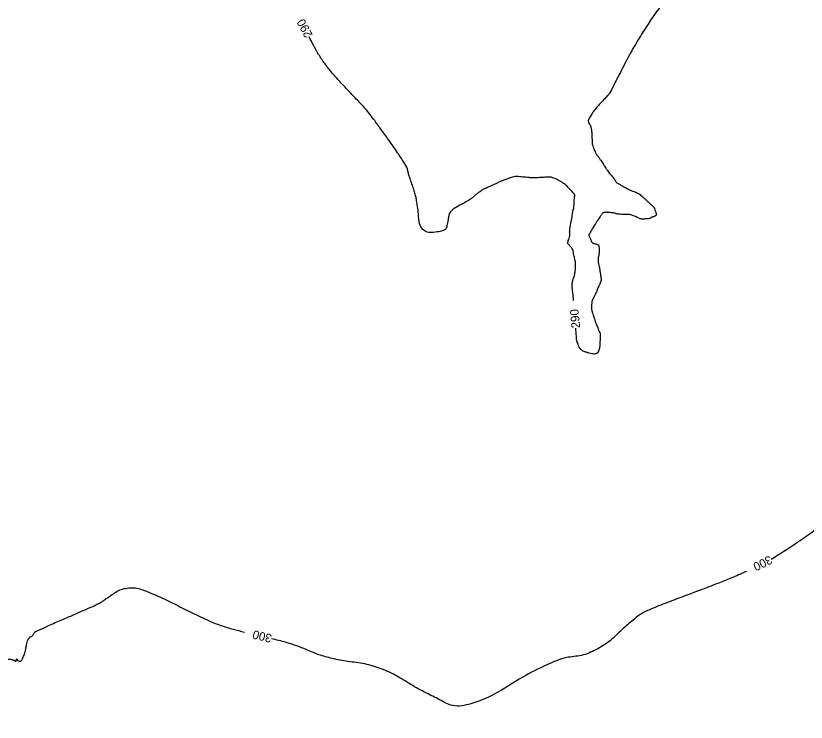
# Model space of a CAD drawing. Extents: x -475575 to -473225, y -1116053 to -1114104.
# Drawn here: x -475129.4 to -474761.3, y -1114773.1 to -1114444.1 of the extents above; entities that cross this region are included whole.
import ezdxf

# ---------------------------------------------------------------- set-up
doc = ezdxf.new("R2010")
doc.units = 0
doc.layers.add('Vrstevnice_hlavni', color=7, linetype='Continuous')
doc.layers.add('Vrstevnice_popis', color=7, linetype='Continuous')

msp = doc.modelspace()

# ---------------------------------------------------------------- linework, layer by layer
at = {"layer": 'Vrstevnice_hlavni'}
for points in [[(-475049.76, -1114348.75), (-475050.03, -1114349.06), (-475050.19, -1114349.2), (-475050.39, -1114349.32), (-475050.61, -1114349.44), (-475051.19, -1114349.58), (-475052.1, -1114349.76), (-475053.36, -1114349.96), (-475056.71, -1114349.42), (-475062.13, -1114348.12), (-475069.64, -1114346.09), (-475075.28, -1114345.23), (-475079.04, -1114345.54), (-475080.93, -1114347.03), (-475082.38, -1114348.43), (-475083.41, -1114349.73), (-475084.01, -1114350.95), (-475084.63, -1114352.12), (-475085.26, -1114353.26), (-475085.91, -1114354.37), (-475086.64, -1114355.71), (-475087.48, -1114357.27), (-475088.4, -1114359.07), (-475090.61, -1114362.26), (-475094.1, -1114366.84), (-475098.87, -1114372.82), (-475103.89, -1114377.82), (-475109.16, -1114381.82), (-475114.67, -1114384.84), (-475118.65, -1114387.53), (-475121.08, -1114389.89), (-475121.98, -1114391.93), (-475122.62, -1114393.48), (-475123, -1114394.53), (-475123.13, -1114395.1), (-475123.36, -1114395.77), (-475123.67, -1114396.56), (-475124.09, -1114397.45), (-475125.66, -1114400.87), (-475128.41, -1114406.82), (-475132.32, -1114415.29), (-475135.87, -1114422.74), (-475139.04, -1114429.17), (-475141.85, -1114434.59), (-475145.43, -1114439.9), (-475149.77, -1114445.11), (-475154.89, -1114450.23), (-475159.45, -1114455.46), (-475163.47, -1114460.8), (-475166.95, -1114466.26), (-475169.43, -1114470.03), (-475170.91, -1114472.1), (-475171.4, -1114472.49), (-475171.83, -1114472.96), (-475172.18, -1114473.51), (-475172.46, -1114474.16), (-475172.97, -1114474.88), (-475173.69, -1114475.68), (-475174.63, -1114476.54), (-475175.57, -1114477.42), (-475176.5, -1114478.32), (-475177.42, -1114479.22), (-475178.83, -1114480.41), (-475180.73, -1114481.89), (-475183.12, -1114483.65), (-475185.77, -1114486.73), (-475188.68, -1114491.12), (-475191.86, -1114496.83), (-475194.68, -1114500.53), (-475197.14, -1114502.21), (-475199.25, -1114501.88), (-475200.83, -1114501.68), (-475201.89, -1114501.59), (-475202.96, -1114501.67)], [(-474824.9, -1114433.68), (-474834.97, -1114447.99), (-474839.72, -1114455.49), (-474844.2, -1114463.32), (-474848.4, -1114471.5), (-474851.28, -1114477.08), (-474852.85, -1114480.06), (-474853.11, -1114480.43), (-474854, -1114481.45), (-474855.52, -1114483.12), (-474857.66, -1114485.43), (-474859.32, -1114487.33), (-474860.49, -1114488.81), (-474861.16, -1114489.87), (-474861.76, -1114490.83), (-474862.28, -1114491.69), (-474862.73, -1114492.45), (-474862.82, -1114493.25), (-474862.57, -1114494.08), (-474861.98, -1114494.94), (-474861.54, -1114496.24), (-474861.26, -1114497.98), (-474861.14, -1114500.14), (-474861.06, -1114501.7), (-474861, -1114502.64), (-474860.98, -1114502.96), (-474860.98, -1114503.23), (-474861, -1114503.44), (-474861.05, -1114503.59), (-474860.87, -1114504.2), (-474860.48, -1114505.27), (-474859.87, -1114506.8), (-474859.38, -1114507.92), (-474859.04, -1114508.62), (-474858.82, -1114508.91), (-474858.41, -1114509.47), (-474857.8, -1114510.3), (-474857, -1114511.41), (-474856.37, -1114512.3), (-474855.93, -1114512.98), (-474855.66, -1114513.44), (-474855.24, -1114514.12), (-474854.66, -1114515.02), (-474853.92, -1114516.15), (-474853.21, -1114517.14), (-474852.52, -1114517.98), (-474851.85, -1114518.69), (-474851.24, -1114519.44), (-474850.69, -1114520.22), (-474850.19, -1114521.03), (-474849.69, -1114521.67), (-474849.16, -1114522.13), (-474848.61, -1114522.43), (-474848.01, -1114522.75), (-474847.37, -1114523.1), (-474846.67, -1114523.48), (-474845.89, -1114523.91), (-474845.04, -1114524.38), (-474844.1, -1114524.9), (-474843.11, -1114525.37), (-474842.07, -1114525.77), (-474840.98, -1114526.13), (-474839.99, -1114526.57), (-474839.09, -1114527.1), (-474838.28, -1114527.73), (-474837.41, -1114528.47), (-474836.48, -1114529.32), (-474835.49, -1114530.28), (-474834.59, -1114531.13), (-474833.78, -1114531.87), (-474833.05, -1114532.49), (-474832.47, -1114533.14), (-474832.04, -1114533.81), (-474831.76, -1114534.5), (-474831.53, -1114535.13), (-474831.34, -1114535.7), (-474831.19, -1114536.22), (-474831.17, -1114536.64), (-474831.26, -1114536.98), (-474831.48, -1114537.22), (-474831.78, -1114537.42), (-474832.15, -1114537.6), (-474832.6, -1114537.73), (-474833.05, -1114537.91), (-474833.5, -1114538.12), (-474833.95, -1114538.37), (-474834.42, -1114538.55), (-474834.92, -1114538.65), (-474835.44, -1114538.69), (-474836.03, -1114538.73), (-474836.71, -1114538.77), (-474837.47, -1114538.82), (-474838.22, -1114538.74), (-474838.95, -1114538.52), (-474839.67, -1114538.17), (-474840.43, -1114537.81), (-474841.25, -1114537.44)], [(-474928.22, -1114539.97), (-474928.27, -1114540.12), (-474928.4, -1114540.71), (-474928.62, -1114541.72), (-474928.93, -1114543.16), (-474930.43, -1114544.18), (-474933.13, -1114544.79), (-474937.03, -1114544.99), (-474939.79, -1114543.67), (-474941.42, -1114540.83), (-474941.91, -1114536.48), (-474942.36, -1114532.94), (-474942.77, -1114530.22), (-474943.15, -1114528.32), (-474943.71, -1114526.16), (-474944.47, -1114523.75), (-474945.43, -1114521.09), (-474946.18, -1114518.79), (-474946.73, -1114516.87), (-474947.08, -1114515.32), (-474948.71, -1114512.31), (-474951.62, -1114507.85), (-474955.81, -1114501.92), (-474959.36, -1114496.95), (-474962.28, -1114492.94), (-474964.57, -1114489.9), (-474966.85, -1114487.11), (-474969.14, -1114484.57), (-474971.42, -1114482.28), (-474974.33, -1114479.23), (-474977.87, -1114475.4), (-474982.03, -1114470.8), (-474985.54, -1114466.36), (-474988.41, -1114462.08), (-474992.84, -1114453.86)], [(-474869.74, -1114576.69), (-474869.76, -1114575.69), (-474869.84, -1114574.75), (-474869.98, -1114573.36), (-474870.19, -1114571.54), (-474870.31, -1114570.17), (-474870.35, -1114569.25), (-474870.3, -1114568.79), (-474870.11, -1114567.94), (-474869.78, -1114566.72), (-474869.3, -1114565.11), (-474868.97, -1114563.53), (-474868.79, -1114561.98), (-474868.75, -1114560.45), (-474868.79, -1114559.19), (-474868.91, -1114558.2), (-474869.1, -1114557.48), (-474869.3, -1114556.56), (-474869.52, -1114555.45), (-474869.75, -1114554.14), (-474870.07, -1114553.08), (-474870.48, -1114552.27), (-474870.98, -1114551.72), (-474871.42, -1114551.23), (-474871.83, -1114550.79), (-474872.18, -1114550.42), (-474872.28, -1114549.76), (-474872.11, -1114548.83), (-474871.68, -1114547.62), (-474871.43, -1114546.62), (-474871.36, -1114545.83), (-474871.46, -1114545.25), (-474871.46, -1114544.41), (-474871.35, -1114543.32), (-474871.15, -1114541.98), (-474870.96, -1114540.89), (-474870.78, -1114540.07), (-474870.63, -1114539.5), (-474870.48, -1114538.71), (-474870.34, -1114537.69), (-474870.21, -1114536.44), (-474870.05, -1114535.43), (-474869.88, -1114534.66), (-474869.69, -1114534.13), (-474869.54, -1114533.24), (-474869.43, -1114532), (-474869.36, -1114530.39), (-474869.28, -1114529.22), (-474869.19, -1114528.49), (-474869.08, -1114528.19), (-474869.02, -1114527.93), (-474869.02, -1114527.71), (-474869.08, -1114527.52), (-474869.17, -1114527.33), (-474869.3, -1114527.14), (-474869.47, -1114526.95), (-474869.96, -1114526.42), (-474870.77, -1114525.54), (-474871.9, -1114524.32), (-474872.67, -1114523.48), (-474873.1, -1114523.03), (-474873.16, -1114522.96), (-474873.57, -1114522.67), (-474874.32, -1114522.15), (-474875.41, -1114521.41), (-474876.53, -1114520.75), (-474877.68, -1114520.18), (-474878.87, -1114519.7), (-474879.76, -1114519.38), (-474880.35, -1114519.22), (-474880.64, -1114519.22), (-474881.72, -1114519.27), (-474883.57, -1114519.36), (-474886.21, -1114519.5), (-474888.47, -1114519.54), (-474890.34, -1114519.49), (-474891.82, -1114519.34), (-474893.29, -1114519.19), (-474894.75, -1114519.04), (-474896.18, -1114518.9), (-474898.64, -1114519.45), (-474902.13, -1114520.71), (-474906.65, -1114522.67), (-474910.02, -1114524.21), (-474912.25, -1114525.34), (-474913.34, -1114526.05), (-474914.45, -1114526.86), (-474915.59, -1114527.79), (-474916.76, -1114528.82), (-474918.59, -1114530.06), (-474921.08, -1114531.51), (-474924.24, -1114533.18), (-474926.43, -1114534.84), (-474927.65, -1114536.5), (-474927.92, -1114538.16), (-474928.11, -1114539.31), (-474928.22, -1114539.97)], [(-474841.25, -1114537.44), (-474842.1, -1114537.05), (-474843.05, -1114536.79), (-474844.09, -1114536.67), (-474845.21, -1114536.67), (-474846.32, -1114536.64), (-474847.41, -1114536.58), (-474848.48, -1114536.49), (-474849.41, -1114536.36), (-474850.18, -1114536.2), (-474850.81, -1114536.01), (-474851.55, -1114535.87), (-474852.39, -1114535.76), (-474853.34, -1114535.69), (-474854.1, -1114535.65), (-474854.68, -1114535.64), (-474855.06, -1114535.66), (-474855.41, -1114535.72), (-474855.71, -1114535.81), (-474855.97, -1114535.95), (-474856.5, -1114536.57), (-474857.29, -1114537.66), (-474858.34, -1114539.23), (-474859.09, -1114540.35), (-474859.52, -1114541.02), (-474859.65, -1114541.23), (-474860.03, -1114541.87), (-474860.66, -1114542.94), (-474861.55, -1114544.43), (-474862.16, -1114545.47), (-474862.51, -1114546.06), (-474862.59, -1114546.19), (-474862.61, -1114546.32), (-474862.57, -1114546.45), (-474862.46, -1114546.58), (-474862.27, -1114546.98), (-474861.99, -1114547.65), (-474861.63, -1114548.59), (-474861.3, -1114549.28), (-474861, -1114549.73), (-474860.72, -1114549.92), (-474860.28, -1114550.11), (-474859.65, -1114550.3), (-474858.85, -1114550.48), (-474858.29, -1114550.77), (-474857.95, -1114551.16), (-474857.84, -1114551.65), (-474857.77, -1114552.3), (-474857.74, -1114553.09), (-474857.74, -1114554.04), (-474857.82, -1114554.96), (-474857.97, -1114555.83), (-474858.19, -1114556.67), (-474858.24, -1114557.69), (-474858.13, -1114558.88), (-474857.86, -1114560.25), (-474857.65, -1114561.36), (-474857.49, -1114562.2), (-474857.4, -1114562.78), (-474857.3, -1114563.45), (-474857.18, -1114564.23), (-474857.06, -1114565.12), (-474856.95, -1114565.86), (-474856.87, -1114566.46), (-474856.8, -1114566.93), (-474856.95, -1114567.68), (-474857.33, -1114568.71), (-474857.93, -1114570.03), (-474858.37, -1114571.02), (-474858.65, -1114571.7), (-474858.76, -1114572.06), (-474859.04, -1114572.71), (-474859.47, -1114573.63), (-474860.07, -1114574.83), (-474860.51, -1114575.73), (-474860.82, -1114576.32), (-474860.98, -1114576.61), (-474861.12, -1114577.17), (-474861.23, -1114578.01), (-474861.32, -1114579.13), (-474861.35, -1114580.03), (-474861.3, -1114580.72), (-474861.19, -1114581.2), (-474860.97, -1114581.99), (-474860.64, -1114583.08), (-474860.2, -1114584.49), (-474859.68, -1114586.01), (-474859.08, -1114587.66), (-474858.4, -1114589.42), (-474857.88, -1114590.7), (-474857.53, -1114591.51), (-474857.33, -1114591.84), (-474857.25, -1114592.75), (-474857.27, -1114594.22), (-474857.4, -1114596.26), (-474857.48, -1114597.68), (-474857.52, -1114598.46)], [(-474857.52, -1114598.46), (-474857.52, -1114598.62), (-474857.65, -1114599.07), (-474857.91, -1114599.8), (-474858.29, -1114600.82), (-474858.95, -1114601.44), (-474859.88, -1114601.66), (-474861.08, -1114601.49), (-474862.35, -1114601.21), (-474863.7, -1114600.82), (-474865.13, -1114600.32), (-474866.25, -1114599.52), (-474867.07, -1114598.42), (-474867.58, -1114597.03), (-474867.93, -1114596.05), (-474868.14, -1114595.49), (-474868.19, -1114595.35), (-474868.26, -1114594.63), (-474868.35, -1114593.34), (-474868.59, -1114589.6)], [(-474777.57, -1114697.19), (-474765.86, -1114689.66), (-474761.25, -1114686.5), (-474757.88, -1114683.93), (-474755.76, -1114681.97), (-474752.41, -1114678.94), (-474747.82, -1114674.87), (-474742, -1114669.74), (-474736.32, -1114665.33), (-474730.78, -1114661.64), (-474725.39, -1114658.67), (-474717.35, -1114656.2), (-474706.67, -1114654.22), (-474693.33, -1114652.74), (-474680.34, -1114650.84), (-474667.68, -1114648.52), (-474655.36, -1114645.78), (-474646.81, -1114643.91), (-474642.03, -1114642.92), (-474641.01, -1114642.79), (-474640.1, -1114642.64), (-474639.29, -1114642.48), (-474638.58, -1114642.31), (-474633.9, -1114641.97), (-474625.25, -1114641.46), (-474612.62, -1114640.8), (-474600, -1114640.58), (-474587.38, -1114640.8), (-474574.75, -1114641.46), (-474566.1, -1114641.88), (-474561.42, -1114642.04), (-474560.71, -1114641.94), (-474559.97, -1114641.94), (-474559.21, -1114642.02), (-474558.42, -1114642.19), (-474556.67, -1114642.43), (-474553.94, -1114642.74), (-474546.56, -1114643.47)], [(-474789.19, -1114702.93), (-474796.4, -1114706.09), (-474802.45, -1114708.51), (-474810.97, -1114711.77), (-474821.93, -1114715.89), (-474830.03, -1114719.02), (-474835.27, -1114721.18), (-474837.63, -1114722.37), (-474841.32, -1114725.09), (-474846.34, -1114729.36), (-474852.68, -1114735.17), (-474859.24, -1114739.39), (-474866.01, -1114742.03), (-474873.01, -1114743.08), (-474882.11, -1114746.45), (-474893.33, -1114752.13), (-474906.67, -1114760.13), (-474917.56, -1114764.56), (-474926.02, -1114765.42), (-474932.04, -1114762.71), (-474938.5, -1114759.44), (-474945.38, -1114755.61), (-474952.69, -1114751.23), (-474960.19, -1114747.95), (-474967.89, -1114745.79), (-474975.79, -1114744.73), (-474982.86, -1114743.28), (-474989.12, -1114741.42), (-474994.56, -1114739.15), (-474999.34, -1114737.35), (-475003.47, -1114736.02), (-475010.41, -1114734.28)], [(-475129.44, -1114744.73), (-475129.31, -1114744.56), (-475129.22, -1114744.44), (-475129.16, -1114744.37), (-475129.14, -1114744.35), (-475129.11, -1114744.22), (-475129.07, -1114743.99), (-475129.02, -1114743.66), (-475128.97, -1114743.58), (-475128.91, -1114743.74), (-475128.84, -1114744.14), (-475128.6, -1114744.44), (-475128.21, -1114744.64), (-475127.64, -1114744.74), (-475127.2, -1114744.7), (-475126.88, -1114744.51), (-475126.68, -1114744.19), (-475126.4, -1114743.63), (-475126.04, -1114742.85), (-475125.61, -1114741.85), (-475125.29, -1114741.03), (-475125.08, -1114740.39), (-475124.98, -1114739.95), (-475124.82, -1114739.15), (-475124.6, -1114737.99), (-475124.33, -1114736.48), (-475124.02, -1114735.31), (-475123.68, -1114734.5), (-475123.31, -1114734.03), (-475122.9, -1114733.63), (-475122.45, -1114733.3), (-475121.97, -1114733.03), (-475121.53, -1114732.64), (-475121.14, -1114732.13), (-475120.8, -1114731.51), (-475118.48, -1114730.18), (-475114.2, -1114728.16), (-475107.93, -1114725.45), (-475102.54, -1114723.1), (-475098.01, -1114721.14), (-475094.36, -1114719.54), (-475091.49, -1114718.18), (-475089.42, -1114717.06), (-475088.14, -1114716.16), (-475086.53, -1114715.05), (-475084.57, -1114713.71), (-475082.29, -1114712.16), (-475079.72, -1114711.12), (-475076.87, -1114710.6), (-475073.73, -1114710.6), (-475068.24, -1114712.3), (-475060.4, -1114715.7), (-475050.2, -1114720.8), (-475042.38, -1114724.56), (-475036.94, -1114726.99), (-475033.88, -1114728.08), (-475030.97, -1114729.03), (-475028.21, -1114729.83), (-475022.98, -1114731.14)], [(-475163.67, -1114740.73), (-475161.8, -1114739.23), (-475160.27, -1114738.1), (-475158.15, -1114736.57), (-475155.44, -1114734.67), (-475153.27, -1114733.13), (-475151.64, -1114731.96), (-475150.55, -1114731.15), (-475148.89, -1114730.16), (-475146.66, -1114728.99), (-475143.85, -1114727.63), (-475141.86, -1114726.7), (-475140.69, -1114726.21), (-475140.32, -1114726.16), (-475139.89, -1114725.96), (-475139.4, -1114725.63), (-475138.84, -1114725.16), (-475138.5, -1114725.38), (-475138.4, -1114726.28), (-475138.52, -1114727.88), (-475138.62, -1114729.1), (-475138.71, -1114729.94), (-475138.78, -1114730.41), (-475138.97, -1114731.29), (-475139.28, -1114732.57), (-475139.72, -1114734.27), (-475140.05, -1114735.78), (-475140.27, -1114737.12), (-475140.39, -1114738.28), (-475140.49, -1114739.57), (-475140.59, -1114741), (-475140.68, -1114742.56), (-475140.73, -1114743.93), (-475140.75, -1114745.11), (-475140.73, -1114746.08), (-475140.77, -1114747.02), (-475140.88, -1114747.91), (-475141.06, -1114748.76), (-475141.28, -1114749.99), (-475141.55, -1114751.59), (-475141.87, -1114753.57), (-475142.13, -1114755.22), (-475142.32, -1114756.53), (-475142.45, -1114757.51), (-475142.56, -1114758.39), (-475142.67, -1114759.18), (-475142.76, -1114759.86), (-475142.87, -1114761.34), (-475143, -1114763.6), (-475143.14, -1114766.66), (-475143.24, -1114768.74), (-475143.3, -1114769.84), (-475143.31, -1114769.96), (-475143.33, -1114770.09), (-475143.34, -1114770.22), (-475143.35, -1114770.36), (-475143.41, -1114770.83), (-475143.5, -1114771.62), (-475143.64, -1114772.74), (-475143.65, -1114773.14), (-475143.54, -1114772.82), (-475143.29, -1114771.79), (-475143.11, -1114771), (-475143, -1114770.45), (-475142.95, -1114770.15), (-475142.89, -1114769.82), (-475142.82, -1114769.47), (-475142.74, -1114769.1), (-475142.47, -1114767.82), (-475142.02, -1114765.64), (-475141.38, -1114762.56), (-475140.83, -1114759.9), (-475140.38, -1114757.68), (-475140.02, -1114755.9), (-475139.71, -1114754.33), (-475139.46, -1114752.97), (-475139.26, -1114751.83), (-475138.98, -1114750.41), (-475138.62, -1114748.71), (-475138.18, -1114746.73), (-475137.77, -1114745.28), (-475137.38, -1114744.36), (-475137.02, -1114743.95), (-475136.78, -1114743.68), (-475136.65, -1114743.56), (-475136.64, -1114743.57), (-475136.16, -1114743.6), (-475135.21, -1114743.64), (-475133.78, -1114743.69), (-475132.58, -1114743.79), (-475131.59, -1114743.92), (-475130.83, -1114744.1), (-475130.26, -1114744.29), (-475129.9, -1114744.49), (-475129.73, -1114744.69), (-475129.58, -1114744.77), (-475129.44, -1114744.73)]]:
    msp.add_spline(points, degree=3, dxfattribs=at)

# ---------------------------------------------------------------- texts
at = {"layer": 'Vrstevnice_popis'}
for s, rotation, p in [(' 290 ', 118.3008, (-474990.35, -1114454.25)), (' 290 ', 95.1105, (-474866.46, -1114590.94)), (' 300 ', 206.276, (-474777.09, -1114694.73)), (' 300 ', 165.9638, (-475008.45, -1114732.71))]:
    msp.add_text(s, height=4, rotation=rotation, dxfattribs=at).set_placement(p)

doc.saveas('drawing.dxf')
